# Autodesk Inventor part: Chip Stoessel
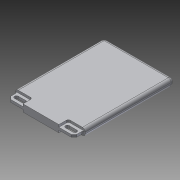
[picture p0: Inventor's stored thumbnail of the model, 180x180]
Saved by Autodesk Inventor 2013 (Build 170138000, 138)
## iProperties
Created: 2013-03
Part Number: Chip Stoessel
Material: Aluminum 6061
Document SubType Name: Modeling
Designer: rYan
Mass: 18.4838 g
Surface Area: 43.0087 cm^2
Volume: 6.82057 cm^3
Density: 2.71 g/cm^3
Author: rYan
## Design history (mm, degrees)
sketch "Sketch1"
  geometry: L1 (-18.5, 26)-(18.5, 26); L2 (18.5, 26)-(18.5, -21); L3 (17.5, -26)-(-17.5, -26); L4 (-18.5, -21)-(-18.5, 26); L5 (-18.5, -21)-(-17.5, -21); L6 (-17.5, -21)-(-17.5, -26); L7 (18.5, -21)-(17.5, -21); L8 (17.5, -21)-(17.5, -26); L9 (0, 36.4)-(0, -36.4) reference; L10 (-25.9, 0)-(25.9, 0) reference; 1 further point
  constraints: 16 end point, 5 perpendicular, 2 parallel, 1 horizontal, 4 other
  dimensions: "d0" = 37 distance between parallel lines of L2 L4; "d2" = 52 distance between parallel lines of L3 L1; "d3" = 5 distance of L5.end L3.end; "d4" = 1 distance of L4.start L5.end
extrude "Extrusion1" new body sketch "Sketch1" stored distance "d5" = 3.8; taper "d6" = 0 deg
fillet "Fillet1" dims "d7" = 1
sketch "Sketch2"
  geometry: L1 (-17.5, -26)-(17.5, -26) reference; L2 (-18.5, 26)-(-18.5, -21) reference; L3 (-18.5, -21)-(-9.5, -21); L4 (-9.5, -21)-(-9.5, -26); L5 (-9.5, -26)-(-18.5, -26); L6 (-18.5, -26)-(-18.5, -21); 1 further point
  constraints: 8 end point, 2 parallel, 1 horizontal, 1 perpendicular, 1 point on line
  dimensions: "d8" = 9 distance between parallel lines of L6 L4
extrude "Extrusion2" cut sketch "Sketch2" distance "d10" = 1.25; taper "d11" = 0 deg
sketch "Sketch3"
  geometry: L1 (-18.5, -21)-(-9.5, -21) reference; L2 (-9.5, -21)-(-9.5, -26) reference; L3 (-15.5, -22.5)-(-11.5, -22.5); L4 (-11.5, -24.5)-(-15.5, -24.5); L5 (-13.5, -22.5)-(-13.5, -24.5); L6 (-15.5, -23.5)-(-11.5, -23.5); A1 r 1 centre (-15.5, -23.5) between (-15.5, -22.5) and (-15.5, -24.5); A2 r 1 centre (-11.5, -23.5) between (-11.5, -24.5) and (-11.5, -22.5); 1 further point
  constraints: 8 end point, 4 point on circle, 4 tangent, 2 centre point, 2 midpoint, 1 horizontal, 1 parallel, 1 perpendicular
  dimensions: "d12" = 2 distance between parallel lines of L4 L3; "d14" = 4 distance of L6.end L6.start; "d15" = 4 distance between parallel lines of L2 L5; "d16" = 2.5 distance between parallel lines of L1 L6
extrude "Extrusion3" cut sketch "Sketch3" stored distance "d17" = 1; taper "d18" = 0 deg
fillet "Fillet2" dims "d19" = 1
mirror "Mirror1"
mirror "Mirror2"
chamfer "Chamfer1" distance "d20" = 1.5; stored, may be unused: second distance "d21" = 2, angle "d22" = 45 deg
fillet "Fillet3" dims "d23" = 1.5
body "Solid1"
